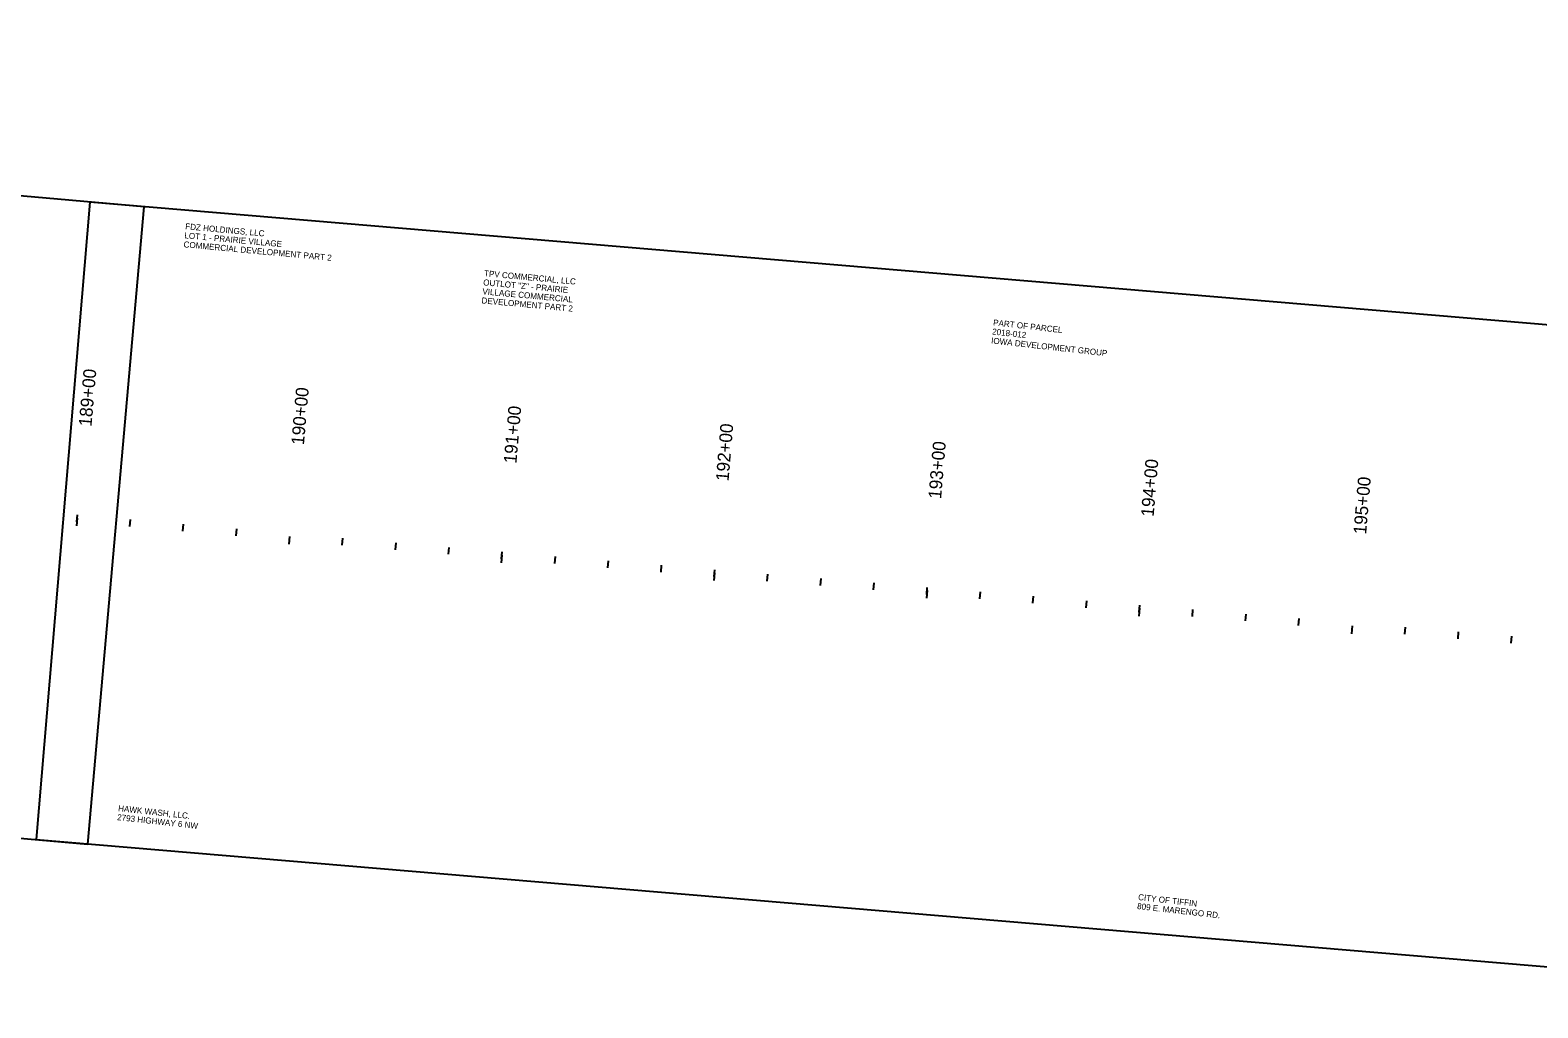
# Model space of a CAD drawing. Extents: x 20499788 to 20505371, y 7953467 to 7954209.
# Drawn here: x 20502583 to 20503290, y 7953593 to 7954051 of the extents above; entities that cross this region are included whole.
import ezdxf

# ---------------------------------------------------------------- set-up
doc = ezdxf.new("R2010")
doc.units = 0
for name, color, linetype in [('NamedBoundary', 7, 'Continuous'), ('Text', 7, 'Continuous'), ('TextAlignmentLrg', 7, 'Continuous'), ('TextAlignmentSml', 7, 'Continuous')]:
    doc.layers.add(name, color=color, linetype=linetype)

msp = doc.modelspace()

# ---------------------------------------------------------------- linework, layer by layer
at = {"layer": 'NamedBoundary'}
for points in [[(20501700.08, 7954051), (20501673.66, 7953752.17), (20502610.5, 7953669.34), (20502636.92, 7953968.17)], [(20502611.39, 7953970.38), (20502586.22, 7953671.43), (20503523.4, 7953592.51), (20503548.57, 7953891.46)]]:
    msp.add_lwpolyline(points, close=True, dxfattribs=at)
at = {"layer": 'TextAlignmentLrg'}
for p, q in [((20502605.28, 7953820.38), (20502605.57, 7953823.64)), ((20502705.07, 7953813.54), (20502704.75, 7953809.88)), ((20502804.53, 7953803.04), (20502804.81, 7953806.3)), ((20502904.18, 7953794.72), (20502904.46, 7953797.99)), ((20503003.84, 7953786.4), (20503004.11, 7953789.67)), ((20503103.49, 7953778.09), (20503103.76, 7953781.35)), ((20503203.3, 7953771.6), (20503202.99, 7953767.94))]:
    msp.add_line(p, q, dxfattribs=at)
at = {"layer": 'TextAlignmentSml'}
for p, q in [((20502605.44, 7953822.21), (20502605.12, 7953818.55)), ((20502630.19, 7953818.21), (20502630.47, 7953821.47)), ((20502655.1, 7953816.04), (20502655.38, 7953819.31)), ((20502680, 7953813.87), (20502680.29, 7953817.14)), ((20502705.07, 7953813.54), (20502704.75, 7953809.88)), ((20502729.81, 7953809.54), (20502730.1, 7953812.8)), ((20502754.72, 7953807.37), (20502755, 7953810.64)), ((20502779.62, 7953805.2), (20502779.91, 7953808.47)), ((20502804.69, 7953804.87), (20502804.37, 7953801.21)), ((20502829.44, 7953800.96), (20502829.72, 7953804.22)), ((20502854.36, 7953798.88), (20502854.63, 7953802.14)), ((20502879.27, 7953796.8), (20502879.54, 7953800.06)), ((20502904.34, 7953796.55), (20502904.03, 7953792.89)), ((20502929.1, 7953792.64), (20502929.37, 7953795.91)), ((20502954.01, 7953790.56), (20502954.28, 7953793.83)), ((20502978.92, 7953788.48), (20502979.2, 7953791.75)), ((20503003.99, 7953788.23), (20503003.69, 7953784.57)), ((20503028.75, 7953784.33), (20503029.02, 7953787.59)), ((20503053.66, 7953782.25), (20503053.94, 7953785.51)), ((20503078.58, 7953780.17), (20503078.85, 7953783.43)), ((20503103.64, 7953779.92), (20503103.34, 7953776.26)), ((20503128.4, 7953776.01), (20503128.68, 7953779.27)), ((20503153.32, 7953773.93), (20503153.59, 7953777.19)), ((20503178.23, 7953771.85), (20503178.5, 7953775.12)), ((20503203.3, 7953771.6), (20503202.99, 7953767.94)), ((20503228.06, 7953767.69), (20503228.33, 7953770.96)), ((20503252.97, 7953765.61), (20503253.24, 7953768.88)), ((20503277.89, 7953763.53), (20503278.16, 7953766.8))]:
    msp.add_line(p, q, dxfattribs=at)

# ---------------------------------------------------------------- texts
at = {"layer": 'Text'}
for s, height, rotation, p in [('LOT 1 - PRAIRIE VILLAGE', 2.8346, 354.76449, (20502655.67, 7953953.42)), ('FDZ HOLDINGS, LLC', 2.8346, 354.76449, (20502656.06, 7953957.65)), ('COMMERCIAL DEVELOPMENT PART 2', 2.8346, 354.76449, (20502655.28, 7953949.19)), ('OUTLOT "Z" - PRAIRIE ', 2.8346, 354.76449, (20502795.78, 7953931.37)), ('TPV COMMERCIAL, LLC', 2.8346, 354.76449, (20502796.17, 7953935.61)), ('VILLAGE COMMERCIAL ', 2.8346, 354.76449, (20502795.39, 7953927.14)), ('DEVELOPMENT PART 2', 2.8346, 354.76449, (20502795, 7953922.9)), ('PART OF PARCEL', 2.8346, 353.65909, (20503034.87, 7953912.56)), ('IOWA DEVELOPMENT GROUP', 2.8346, 353.65909, (20503033.93, 7953904.11)), ('2018-012', 2.835, 353.65909, (20503034.4, 7953908.33)), ('HAWK WASH, LLC.', 2.8346, 353.70825, (20502624.58, 7953684.79)), ('2793 HIGHWAY 6 NW', 2.8346, 353.70825, (20502624.11, 7953680.57)), ('CITY OF TIFFIN', 2.8346, 353.49015, (20503102.86, 7953643.11)), ('809 E. MARENGO RD.', 2.8346, 353.49015, (20503102.38, 7953638.89))]:
    msp.add_text(s, height=height, rotation=rotation, dxfattribs=at).set_placement(p)
at = {"layer": 'TextAlignmentLrg'}
for s, rotation, p in [('190+00', 85.02642, (20502711.8, 7953856.28)), ('195+00', 85.22957, (20503209.88, 7953814.37))]:
    msp.add_text(s, height=6.012, rotation=rotation, dxfattribs=at).set_placement(p)
at = {"layer": 'TextAlignmentSml'}
for s, rotation, p in [('189+00', 85.02642, (20502612.18, 7953864.95)), ('190+00', 85.02642, (20502711.8, 7953856.28)), ('191+00', 85.02642, (20502811.43, 7953847.61)), ('192+00', 85.22957, (20502910.92, 7953839.32)), ('193+00', 85.22957, (20503010.58, 7953831)), ('194+00', 85.22957, (20503110.23, 7953822.68)), ('195+00', 85.22957, (20503209.88, 7953814.37))]:
    msp.add_text(s, height=6.012, rotation=rotation, dxfattribs=at).set_placement(p)

doc.saveas('drawing.dxf')
